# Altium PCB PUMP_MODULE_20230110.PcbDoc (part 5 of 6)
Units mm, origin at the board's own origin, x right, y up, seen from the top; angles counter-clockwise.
Board outline 260.15 x 142.01 mm, 4 copper layers (Top Layer, Mid-Layer 1, Mid-Layer 2, Bottom Layer); 422 components, 240 nets, 1746 pads, 416 vias.
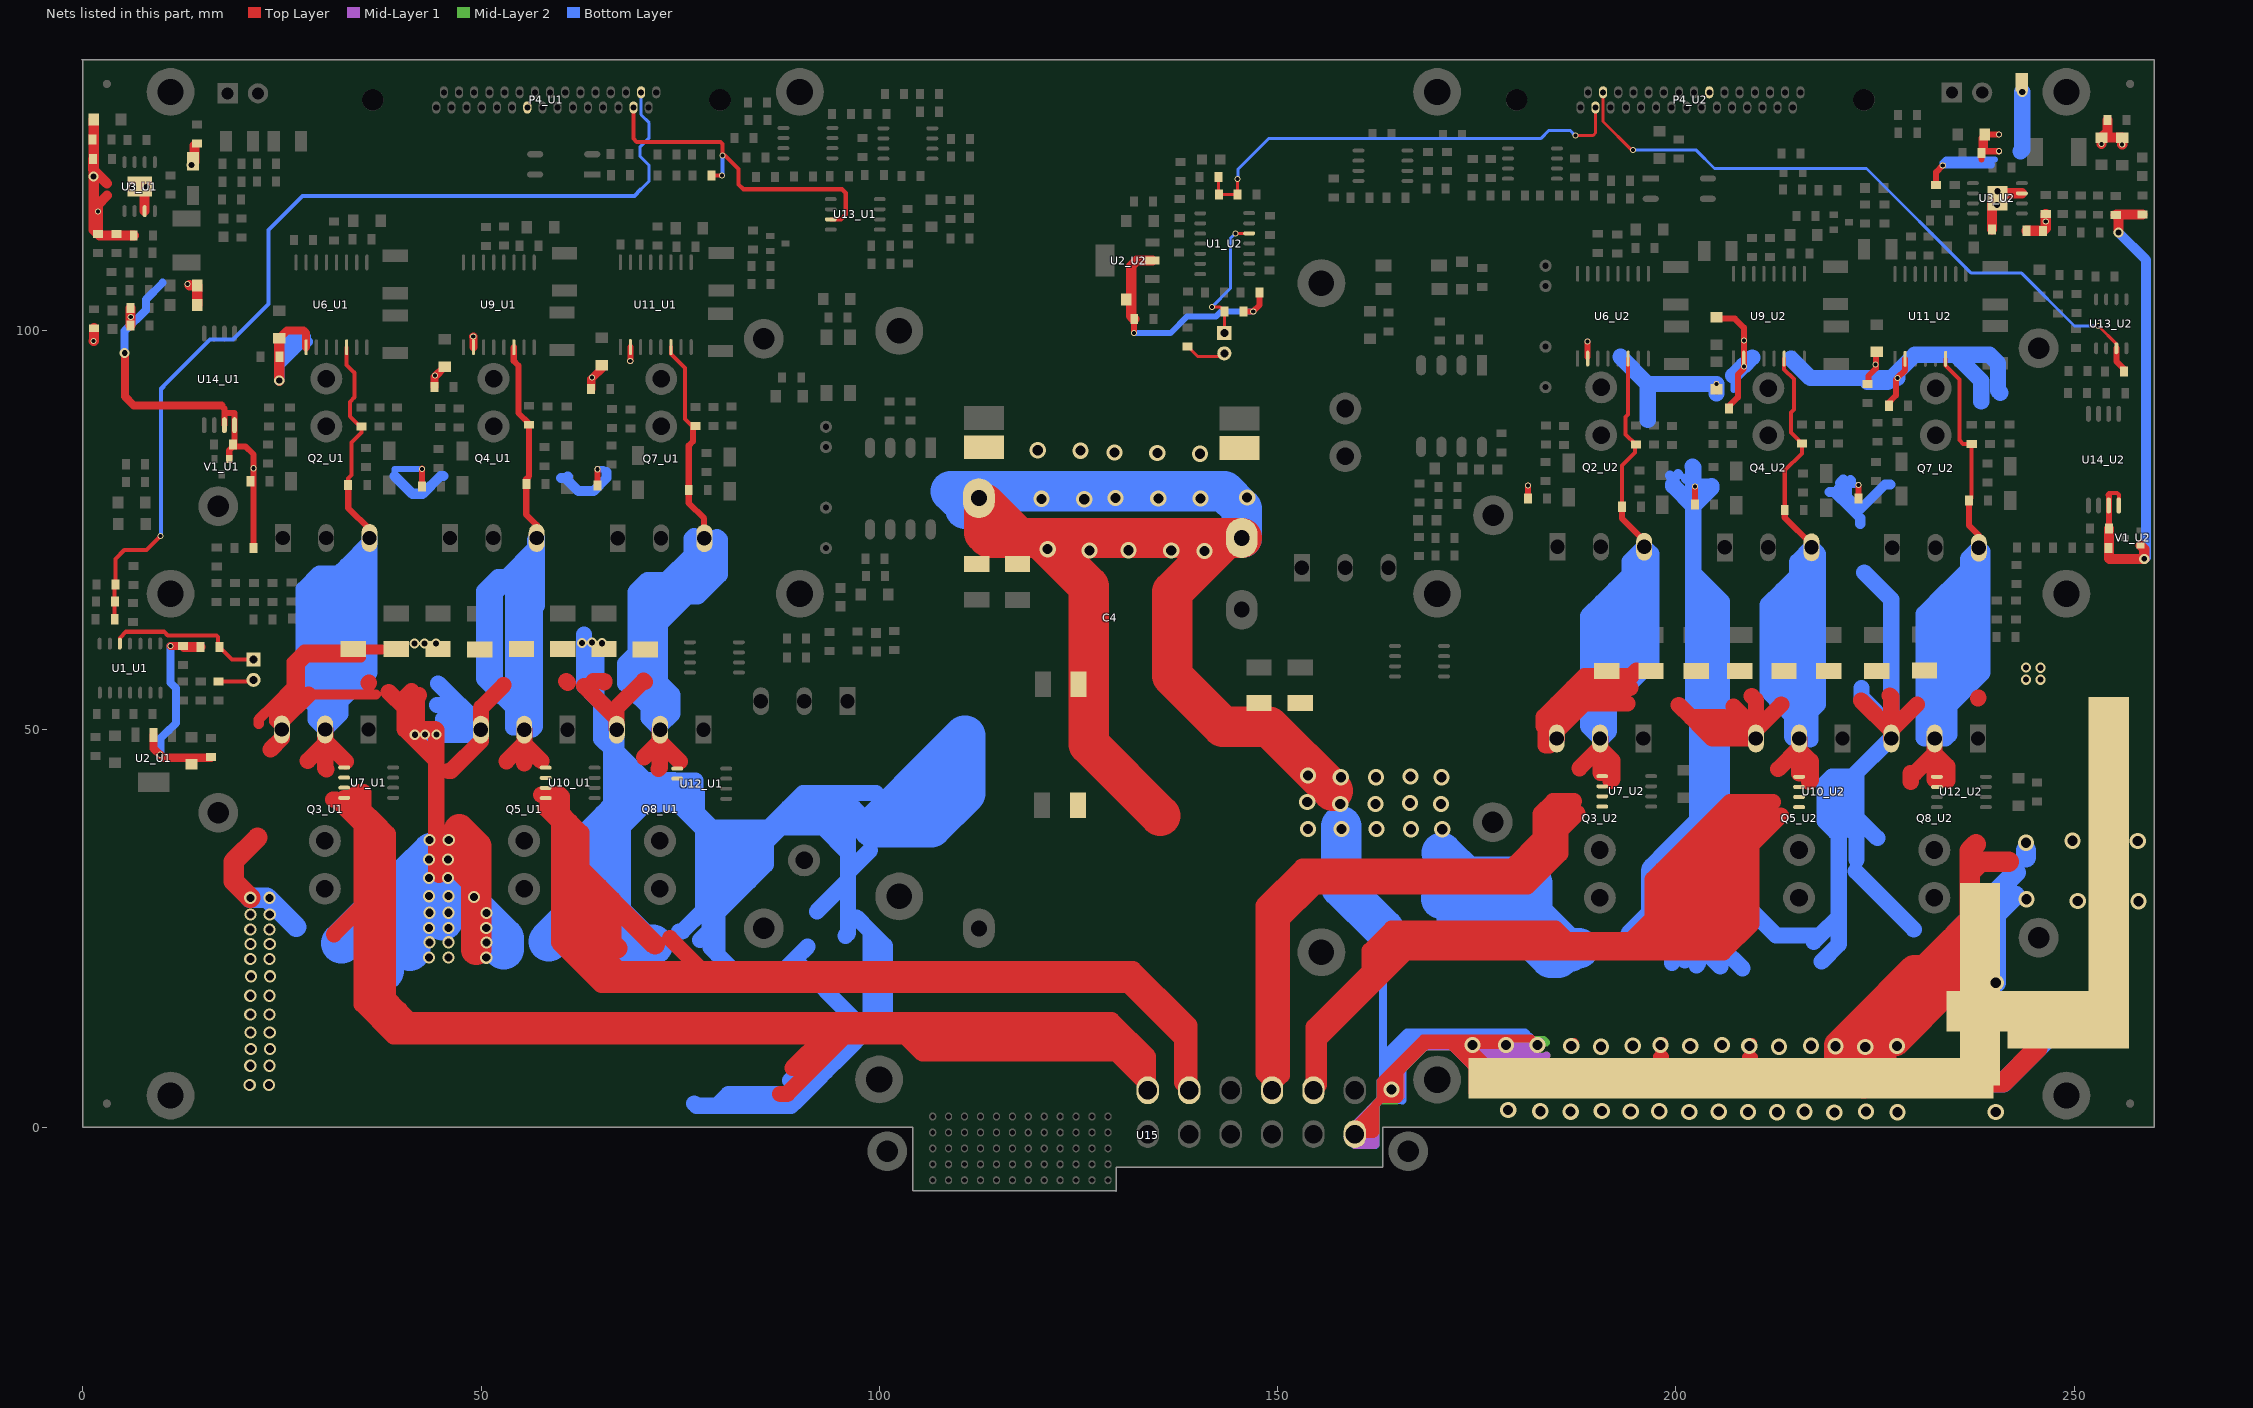
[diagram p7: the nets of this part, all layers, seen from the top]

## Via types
v1: diameter 0.762, hole 0.508, Top Layer to Bottom Layer, 208 vias
v2: diameter 2.032, hole 1.27, Top Layer to Bottom Layer, 78 vias
v3: diameter 1.27, hole 0.762, Top Layer to Bottom Layer, 61 vias
v4: diameter 1.524, hole 1.016, Top Layer to Bottom Layer, 53 vias
v5: diameter 1.27, hole 0.711, Top Layer to Bottom Layer, 16 vias

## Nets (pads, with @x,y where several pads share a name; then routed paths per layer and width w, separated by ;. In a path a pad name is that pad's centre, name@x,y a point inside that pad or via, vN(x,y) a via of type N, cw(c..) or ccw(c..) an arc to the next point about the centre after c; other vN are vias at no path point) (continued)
PGND: C4.2 C15_U1.1 C15_U2.1 C16_U1.1 C16_U2.1 C17.1 C18.1 C19_U1.2 C19_U2.2 C20_U1.1 C20_U2.1 C21_U1.2 C21_U2.2 C22_U1.2 C22_U2.2 C24_U1.2 C24_U2.2 C25_U1.1 C25_U2.1 C26_U1.1 C26_U2.1 C27_U1.1 C27_U2.1 C29_U1.1 C29_U2.1 C30_U1.1 C30_U2.1 C43_U1.2 C43_U2.2 C44_U1.2 C44_U2.2 C51_U1.2 C51_U2.2 C52_U1.2 C52_U2.2 C68_U1.2 C68_U2.2 C69_U1.1 C69_U2.1 C70_U1.1 C70_U2.1 C71_U1.1 C71_U2.1 C72_U1.1 C72_U2.1 C73.1 C74.1 C75.1 C76.1 C77_U1.1 C77_U2.1 C78_U1.1 C78_U2.1 D2_U1.1 D2_U2.1 pad.@186.665,6.172 pad.@210.414,6.172 pad.@227.203,6.172 pad.@238.176,17.958 pad.@244.145,14.58 pad.@249.276,12.446 pad.@254.356,24.765 pad.@254.356,41.326 Q3_U1.3 Q3_U2.3 Q5_U1.3 Q5_U2.3 Q8_U1.3 Q8_U2.3 R16_U1.2 R16_U2.2 R21_U1.2 R21_U2.2 R22_U1.1 R22_U2.1 R24_U1.2 R24_U2.2 R25_U1.1 R25_U2.1 R37_U1.1 R37_U2.1 R54_U1.1 R54_U2.1 R68_U1.1 R68_U2.1 R78_U1.2 R78_U2.2 U3_U1.7 U3_U1.9 U3_U2.7 U3_U2.9 U6_U1.2 U6_U2.2 U9_U1.2 U9_U2.2 U11_U1.2 U11_U2.2 U14_U1.3 U14_U1.4 U14_U2.3 U14_U2.4 U15.12 V1_U1.1 V1_U2.1 | length 2564
  Top Layer w0.508: C69_U2.1@254.305,72.72 C69_U2.1@254.33,72.746 ; U14_U2.3@254.33,78.08 254.33,79.375 254.229,79.477 254.381,79.629 255.397,79.629 255.6,79.426 U14_U2.4@255.6,78.08
  Top Layer w0.762: 17.399,90.627 17.78,90.246 17.78,89.433 ; U14_U1.3@17.78,88.163 17.78,89.433 ; V1_U1.1@18.39,83.896 18.39,84.988 C69_U1.1@18.898,85.496 ; R37_U1.1@21.057,81.128 R37_U1.1@21.438,80.747 ; R78_U1.2@21.438,72.746 R37_U1.1@21.438,80.747 ; 24.663,95.58 24.79,95.58 ; R54_U1.1@42.57,80.467 42.57,82.702 v1(42.596,82.677) ; v1(64.618,82.626) 64.618,82.677 64.643,82.652 R68_U1.1@64.643,80.569 ; v1(68.732,96.241) 68.758,96.266 U11_U1.2@68.758,97.968 ; R37_U2.1@181.407,78.943 v1(181.407,80.569) ; U6_U2.2@188.925,96.723 v1(188.925,98.654) ; R54_U2.1@202.387,78.181 v1(202.387,80.442) ; C43_U2.2@205.08,92.405 v1(205.08,93.32) ; C51_U2.2@205.08,101.702 205.232,101.549 207.391,101.549 208.534,100.406 v1(208.534,98.781) v1(208.534,95.529) 208.534,95.504 208.509,95.479 208.509,95.25 207.772,94.513 207.772,91.669 C44_U2.2@206.68,90.576 ; R68_U2.1@222.936,78.943 v1(222.936,80.67) ; C68_U2.2@224.18,93.751 224.18,94.361 225.12,95.301 C19_U2.2@225.12,97.358 ; C52_U2.2@226.644,90.907 227.635,91.897 227.635,93.904 v1(227.813,94.082) ; v1@227.8,94.094 228.778,95.072 U11_U2.2@228.778,96.495 ; R24_U2.2@232.664,118.313 232.664,119.939 v1(233.502,120.777) ; 238.379,121.539 C25_U2.1@238.379,122.352 ; v1(240.538,122.555) C25_U2.1@238.582,122.555 ; v1(240.538,124.638) C24_U2.2@238.785,124.638 ; 254.33,79.375 254.381,79.324 R78_U2.2@254.381,75.209 ; 17.78,89.433 18.059,89.713 19.025,89.713 19.05,89.687 U14_U1.4@19.05,88.163 19.05,85.649 C69_U1.1@18.898,85.496 ; C69_U1.1@18.898,85.496 20.422,85.496 21.438,84.48 R37_U1.1@21.438,80.747 ; C25_U2.1@238.379,122.352 C25_U2.1@238.582,122.555 ; C25_U2.1@238.379,122.352 238.379,124.231 C24_U2.2@238.785,124.638 ; C25_U2.1@238.582,122.555 238.785,122.758 C24_U2.2@238.785,124.638
  Top Layer w1.016: v5(5.258,97.231) 5.283,97.206 5.283,91.745 6.401,90.627 17.399,90.627 ; C43_U1.2@24.663,99.085 25.629,100.051 27.711,100.051 28.042,99.72 U6_U1.2@28.042,97.942 ; C44_U1.2@44.145,92.964 44.145,94.209 C51_U1.2@45.441,95.504 ; v1(49.022,99.314) 49.047,99.289 U9_U1.2@49.047,97.942 ; C52_U1.2@63.83,92.71 63.83,93.955 65.354,95.479 C19_U1.2@65.354,95.733 ; pad.@174.473,7.569 171.679,10.363 ; pad.@176.098,6.934 176.098,7.315 174.6,8.814 174.473,8.941 ; pad.@176.53,7.798 174.6,9.728 v2@174.473,9.855 ; v2@178.943,10.109 v2(178.689,10.363) v2(174.473,10.363) ; v2(182.626,10.363) 181.839,11.151 168.758,11.151 ; U15.12@159.741,-0.837 159.741,0.204 162.286,2.748 ; U15.12@159.741,-0.837 U15.12@160.934,-0.837 ; U15.12@159.741,-0.837 162.286,1.707 ; U15.12@160.934,-0.837 162.028,-0.837 162.286,-0.579 162.286,0.514 ; U15.12@160.934,-0.837 162.286,0.514 ; 162.286,0.514 162.286,1.707 ; 162.286,1.707 162.286,2.748 ; 162.286,2.748 162.286,2.894 162.973,3.581 ; 162.973,3.581 162.973,5.849 168.275,11.151 168.758,11.151 ; 162.973,3.581 163.373,3.981 163.373,5.766 164.313,6.706 ; 162.973,3.581 163.119,3.581 ; 163.119,3.581 165.1,3.581 165.303,3.785 165.303,6.96 ; 163.119,3.581 v2(164.313,4.775) 164.313,6.706 ; 164.313,6.706 165.303,7.696 ; 165.303,6.96 165.303,7.696 ; 165.303,6.96 168.707,10.363 ; 165.303,7.696 167.97,10.363 ; 167.97,10.363 168.707,10.363 ; 167.97,10.363 168.758,11.151 ; 168.707,10.363 171.679,10.363 ; 171.679,10.363 173.05,10.363 ; 173.05,10.363 174.473,8.941 ; 173.05,10.363 v2(174.473,10.363) ; 174.473,8.941 v2@174.473,9.855 ; v2@174.473,9.855 v2(174.473,10.363)
  Top Layer w1.27: C26_U1.1@1.295,121.59 1.295,120.244 1.372,120.167 ; v1(1.372,98.73) 1.422,98.781 R16_U1.2@1.422,100.33 ; C24_U1.2@1.372,126.517 1.372,120.167 ; 3.023,118.516 1.372,120.167 ; 3.048,116.992 1.93,115.875 v1(1.93,114.986) ; C29_U1.1@5.969,102.87 5.994,102.845 C30_U1.1@5.994,100.686 ; C27_U1.1@6.401,111.963 2.108,111.963 R22_U1.1@1.93,112.141 ; U3_U1.9@7.163,118.11 7.772,117.5 U3_U1.7@7.772,115.037 ; v1@13.411,105.74 13.437,105.715 C21_U1.2@14.376,105.715 C22_U1.2@14.376,103.251 ; D2_U1.1@14.046,121.209 C25_U1.1@14.046,123.292 ; 22.098,50.648 22.098,51.232 24.003,53.137 ; C43_U1.2@24.663,99.085 24.663,95.58 v3(24.663,93.751) v3@24.689,93.726 ; 34.95,59.03 28.296,59.03 28.27,59.055 27.28,58.064 27.28,55.194 26.416,54.331 ; 36.779,54.331 28.346,54.331 26.416,54.331 ; 37.49,60.02 27.788,60.02 26.238,58.471 26.238,55.372 24.003,53.137 ; 174.473,8.941 174.473,7.569 pad.@174.6,7.442 ; v2@174.6,9.728 174.6,8.814 pad.@174.6,7.442 ; v2(186.868,10.236) v2@187.198,10.566 ; 197.764,8.915 198.526,8.915 198.069,9.373 v2(198.069,10.338) v2@198.399,10.668 ; 208.915,8.814 209.677,8.814 209.22,9.271 v2(209.22,10.236) v2@209.55,10.566 ; 219.735,8.763 220.497,8.763 220.04,9.22 v2(220.04,10.185) v2@220.37,10.516 ; C26_U2.1@239.7,112.751 239.7,116.002 U3_U2.9@240.36,116.662 240.97,117.272 U3_U2.7@243.434,117.272 ; R22_U2.1@244.043,112.573 246.024,112.573 R25_U2.1@246.075,112.522 246.431,112.878 v1(246.431,113.716) C27_U2.1@246.431,114.681 ; v1(253.416,123.444) C21_U2.2@253.416,124.257 ; C30_U2.1@254.178,126.492 254.178,125.019 C21_U2.2@253.416,124.257 ; R78_U2.2@254.381,75.209 254.356,75.184 254.356,71.45 254.432,71.374 v5(258.801,71.374) 258.801,72.593 V1_U2.1@258.318,73.076 ; C29_U2.1@255.219,114.554 C29_U2.1@255.295,114.63 ; v5(255.575,112.344) 255.575,114.351 C29_U2.1@255.295,114.63 ; v1(256.032,123.419) C22_U2.2@256.032,124.231 256.007,124.257 C21_U2.2@253.416,124.257 ; R16_U2.2@258.572,114.63 C29_U2.1@255.295,114.63 ; 1.372,115.545 1.372,120.167 ; 1.372,115.545 1.372,112.7 R22_U1.1@1.93,112.141 ; 1.372,115.545 v1(1.93,114.986) ; R22_U1.1@1.93,112.141 v1(1.93,114.986) ; 24.003,52.019 24.003,50.997 25,50 25,50.984 Q3_U1.3@25,51.022 ; 24.003,52.019 Q3_U1.3@25,51.022 ; 24.003,52.019 24.003,53.137 ; Q3_U1.3@25,51.022 25,52.915 26.416,54.331 ; pad.@174.6,7.442 174.6,4.369 175.362,4.369 174.904,4.826 174.904,5.791 175.235,6.121 175.235,6.807 pad.@174.6,7.442
  Top Layer w2.032: 23.571,47.447 25,48.876 Q3_U1.3@25,50 ; Q3_U1.3@25,50.984 28.346,54.331 ; 35.88,55.794 35.916,55.829 ; 38.405,54.661 40.399,52.667 ; 41.275,54.788 40.399,53.911 40.399,52.667 ; 42.215,54.254 41.961,54 41.961,50 ; 44.729,31.725 44.374,32.08 44.374,46.025 ; 45.974,44.729 45.949,44.729 45.923,44.755 46.228,44.755 50,48.527 50,52.692 52.832,55.524 ; 60.706,56.007 60.88,55.833 ; 62.941,55.423 Q8_U1.3@67,51.364 ; 64.135,56.058 65.456,56.058 65.456,55.88 ; Q8_U1.3@67,50 Q8_U1.3@67,51.364 ; 70.561,55.931 70.409,56.083 67,52.674 Q8_U1.3@67,51.364 ; 189.255,53.213 188.493,53.213 ; 193.929,53.213 188.493,53.213 ; 194.259,55.194 187.046,55.194 ; 195.047,57.328 194.412,56.693 188.544,56.693 187.046,55.194 ; 200.355,53.035 201.905,51.486 ; 207.239,52.832 Q5_U2.3@210.041,50.029 ; 209.525,54.153 210.041,53.636 Q5_U2.3@210.041,50.029 ; 213.233,53.086 Q5_U2.3@210.041,49.894 ; 223.241,53.594 Q8_U2.3@227.041,49.793 ; 226.847,54.229 227.041,54.035 Q8_U2.3@227.041,49.876 ; Q8_U2.3@227.041,48.83 Q8_U2.3@227.041,49.793 ; 230.251,53.086 Q8_U2.3@227.041,49.876 ; 237.921,53.873 237.998,53.95 ; 40.399,50 44.374,46.025 ; 40.399,50 41.961,50 ; 40.399,50 40.399,52.667 ; 41.961,50 44.259,50 44.374,49.886 44.374,46.025 ; Q3_U2.3@185.041,49.761 185.041,51.234 ; Q3_U2.3@185.041,49.761 188.493,53.213 ; Q3_U2.3@185.041,49.761 Q3_U2.3@185.041,48.83 184.167,47.955 183.667,47.955 183.667,50.114 183.413,50.368 183.413,51.562 185.041,53.19 ; 185.041,51.234 185.041,53.19 ; 185.041,51.234 187.02,53.213 188.493,53.213 ; 185.041,53.19 187.046,55.194 ; 201.905,51.486 203.467,49.924 ; 201.905,51.486 205.969,51.486 207.531,49.924 ; 203.467,49.924 204.561,48.83 208.625,48.83 ; 203.467,49.924 207.531,49.924 ; 207.531,49.924 208.625,48.83 ; 208.625,48.83 Q5_U2.3@210.041,48.83 Q5_U2.3@210.041,49.894 ; Q5_U2.3@210.041,49.894 Q5_U2.3@210.041,50.029 ; Q8_U2.3@227.041,49.793 Q8_U2.3@227.041,49.876
  Top Layer w2.54: v4(21.031,28.829) 18.948,30.912 18.948,33.401 21.946,36.398 ; pad.@227.559,5.639 241.071,5.639 pad.@245.364,9.931 ; v2(227.762,10.211) 234.772,17.221 234.772,21.641 ; 234.772,23.19 234.772,24.079 236.88,26.187 236.88,31.953 ; 237.668,35.56 236.88,34.773 236.88,31.953 ; 241.833,33.35 238.277,33.35 236.88,31.953
  Top Layer w3.81: 45.491,34.849 45.542,34.849 49.403,30.988 ; 47.269,37.44 49.403,35.306 49.403,30.988 ; 49.403,22.276 49.403,30.988 ; pad.@223.571,5.512 v2@223.571,10.439 ; pad.@225.806,7.772 225.806,12.675 ; 234.772,21.641 225.806,12.675 ; 234.772,23.19 231.343,19.761 229.921,19.761 223.571,13.411 ; v2@223.571,10.439 221.894,8.763 220.497,8.763 220.497,10.338 223.571,13.411 ; v2@223.571,10.439 225.806,12.675 ; v2@223.571,10.439 223.571,13.411
  Top Layer w5.08: 117.5,74 113.182,78.318 113.182,74.651 113.833,74 C4.2@143.545,74 ; 120.208,74 126.289,67.92 126.289,48.133 135.28,39.141 ; C4.2@145.5,74 C4.2@143.545,74 ; 156.947,42.291 148.92,50.317 143.129,50.317 136.754,56.693 136.754,67.234 136.779,67.234 C4.2@143.545,74
  Mid-Layer 1 w1.016: U15.12@158.775,-1.27 159.69,-2.184 162.179,-2.184 162.286,-2.078 162.286,-0.833 ; U15.12@159.7,-0.837 160.438,-1.575 161.544,-1.575 162.286,-0.833 ; 165.456,6.807 165.456,5.105 ; 168.834,10.185 171.806,10.185 170.891,11.1 ; 172.06,10.185 173.304,10.185 174.676,8.814 183.54,8.814 183.744,9.017 ; U15.12@159.741,-0.837 159.741,0.349 162.286,2.894 ; U15.12@159.741,-0.837 162.286,1.707 ; U15.12@159.741,-0.837 160.935,-0.837 162.286,0.513 ; 162.286,-0.833 162.286,0.513 ; 162.286,0.513 162.286,1.707 ; 162.286,1.707 162.286,2.894 ; 162.286,2.894 162.944,3.553 ; 162.944,3.553 162.944,5.82 163.551,6.426 ; 162.944,3.553 v2@163.551,4.159 ; 162.944,3.553 163.551,3.553 ; 163.551,3.553 164.385,3.553 ; 163.551,3.553 v2@163.551,4.159 ; v2@163.551,4.159 163.551,6.426 ; v2@163.551,4.159 164.167,4.775 v2(164.313,4.775) ; 163.551,6.426 168.224,11.1 168.732,11.1 ; v2(164.313,4.775) 165.125,4.775 165.456,5.105 ; v2(164.313,4.775) v2@164.313,5.258 ; v2(164.313,4.775) 164.313,3.734 164.44,3.607 164.385,3.553 ; v2@164.313,5.258 164.313,6.68 164.821,7.188 ; v2@164.313,5.258 164.821,5.766 164.821,7.188 ; 164.385,3.553 165.147,3.553 165.456,3.861 165.456,5.105 ; 164.821,7.188 168.732,11.1 ; 168.732,11.1 170.891,11.1 ; 170.891,11.1 181.889,11.1 v2(182.626,10.363) ; v2(182.626,10.363) 181.635,9.373 175.463,9.373 v2(174.473,10.363) v2(178.689,10.363) v2(182.626,10.363) ; 165.456,7.112 168.529,10.185 168.072,10.185 165.456,7.569 165.456,7.112
  Mid-Layer 1 w1.27: 172.06,10.185 175.362,6.883 175.362,6.248
  Mid-Layer 2 w1.016: U15.12@158.877,-1.372 159.664,-2.159 162.23,-2.159 162.286,-2.103 162.286,-0.859 ; U15.12@159.7,-0.837 159.7,0.308 162.286,2.894 ; 162.806,3.414 163.347,3.414 ; 162.966,3.574 162.966,5.766 163.5,6.299 ; 165.405,6.7 165.405,3.962 165.049,3.607 ; 168.865,10.16 171.958,10.16 ; 175.158,5.385 175.158,6.96 171.958,10.16 ; 183.617,8.915 174.473,8.915 173.228,10.16 171.958,10.16 ; 183.718,10.643 183.388,10.973 171.145,10.973 ; U15.12@159.741,-0.837 159.741,0.255 162.286,2.799 ; U15.12@159.741,-0.837 U15.12@159.818,-0.914 ; U15.12@159.741,-0.837 159.996,-0.837 162.286,1.453 ; U15.12@159.818,-0.914 160.098,-1.194 161.95,-1.194 162.286,-0.859 ; U15.12@159.818,-0.914 161.315,-0.914 162.286,0.056 ; 162.286,-0.859 162.286,0.056 ; 162.286,0.056 162.286,1.453 ; 162.286,1.453 162.286,2.799 ; 162.286,2.799 162.286,2.894 ; 162.286,2.894 163.5,4.108 ; 163.347,3.414 164.338,3.414 ; 163.347,3.414 163.5,3.567 163.5,4.108 ; 163.5,4.108 163.5,6.299 ; 163.5,4.108 164.167,4.775 v2(164.313,4.775) ; 163.5,6.299 164.313,7.112 ; v2(164.313,4.775) v2@164.313,5.613 ; v2(164.313,4.775) 165.024,4.775 165.049,4.801 165.049,3.607 ; v2(164.313,4.775) 164.338,4.75 164.338,3.414 ; v2@164.313,5.613 164.313,7.112 ; v2@164.313,5.613 164.795,6.096 164.795,7.595 ; 164.313,7.112 164.795,7.595 ; 164.338,3.414 164.857,3.414 165.049,3.607 ; 164.795,7.595 168.173,10.973 171.145,10.973 ; 171.145,10.973 171.958,10.16 ; 165.405,7.061 168.504,10.16 168.097,10.16 165.405,7.468 165.405,7.061 ; v2@174.473,10.008 174.777,9.703 181.966,9.703 v2(182.626,10.363) v2(178.689,10.363) v2(174.473,10.363) v2@174.473,10.008
  Bottom Layer w0.762: 39.167,81.763 39.167,82.652 39.192,82.677 v1(42.596,82.677) ; v1(64.618,82.626) 65.38,82.626 65.761,82.245 ; 207.239,92.583 207.239,94.234 v1(208.534,95.529) 208.483,95.58 v1@208.432,95.631 ; 221.488,80.594 221.564,80.67 v1(222.936,80.67) ; 239.7,120.879 239.598,120.777 v1(233.502,120.777) 233.502,121.107 233.934,121.539 240.03,121.539
  Bottom Layer w1.016: v5(5.258,97.231) 5.258,99.974 7.925,102.641 7.925,103.937 10.033,106.045 ; U15.12@158.902,-1.422 159.664,-2.184 161.047,-2.184 ; U15.12@159.284,-0.837 U15.12@159.7,-0.837 161.047,-2.184 ; 163.525,20.676 163.22,20.371 163.22,8.915 ; v2@163.805,4.191 163.779,4.216 v2@163.779,4.387 ; 175.387,8.128 174.473,9.042 ; U15.12@159.741,-0.837 159.741,0.28 161.011,1.549 ; U15.12@159.741,-0.837 160.479,-1.575 161.798,-1.575 162.286,-1.087 ; U15.12@159.741,-0.837 161.011,0.432 161.011,1.549 ; U15.12@159.741,-0.837 U15.12@160.529,-0.837 ; U15.12@160.529,-0.837 161.977,-0.837 162.286,-0.528 ; U15.12@160.529,-0.837 161.62,0.254 161.62,2.159 ; 161.011,1.549 161.62,2.159 ; 161.047,-2.184 162.286,-2.184 162.286,-1.087 ; 161.62,2.159 161.62,2.228 162.286,2.894 ; 162.286,-1.087 162.286,-0.528 ; 162.286,-0.528 162.286,2.894 ; 162.286,2.894 162.881,3.489 ; 162.881,3.489 163.068,3.676 ; 162.881,3.489 162.941,3.429 164.135,3.429 ; 163.068,3.676 v2@163.779,4.387 ; 163.068,3.676 163.068,4.623 163.22,4.775 ; 163.22,4.775 163.22,8.915 ; 163.22,4.775 v2@163.779,4.775 ; 163.22,8.915 166.243,11.938 167.335,11.938 ; v2@163.779,4.387 v2@163.779,4.775 ; v2@163.779,4.387 v2@164.167,4.775 ; v2@163.779,4.775 163.779,8.357 164.313,7.823 ; v2@163.779,4.775 v2@164.167,4.775 ; 164.135,3.429 165.151,3.429 ; 164.135,3.429 164.313,3.607 v2(164.313,4.775) ; v2@164.167,4.775 v2(164.313,4.775) ; v2(164.313,4.775) 164.313,7.671 ; v2(164.313,4.775) 165.075,4.775 v2@165.151,4.699 ; 164.313,7.671 167.475,10.833 ; 164.313,7.671 164.313,7.823 ; 164.313,7.823 164.313,8.915 167.335,11.938 ; 165.151,3.429 165.644,3.429 165.659,3.414 165.659,7.315 168.631,10.287 ; 165.151,3.429 v2@165.151,4.699 ; v2@165.151,4.699 165.151,7.214 168.224,10.287 168.631,10.287 ; 167.335,11.938 181.051,11.938 181.661,11.328 ; 167.475,10.833 171.59,10.833 ; 167.475,10.833 167.97,11.328 171.094,11.328 ; 168.631,10.287 172.136,10.287 ; 171.094,11.328 181.661,11.328 ; 171.094,11.328 171.59,10.833 ; 171.59,10.833 174.003,10.833 v2(174.473,10.363) ; 171.59,10.833 172.136,10.287 ; 172.136,10.287 172.136,9.957 174.473,7.62 174.473,9.042 ; 172.136,10.287 173.228,10.287 174.473,9.042 ; 174.473,9.042 v2(174.473,10.363) ; v2(174.473,10.363) v2(178.689,10.363) v2(182.626,10.363) 181.661,11.328
  Bottom Layer w1.27: v3(24.663,93.751) 24.663,95.682 ; 24.714,96.749 24.714,96.977 ; 27.991,99.289 26.035,99.289 24.714,97.968 24.714,96.977 ; 28.296,98.628 27.61,98.628 ; 39.167,81.763 41.377,79.553 42.672,79.553 44.907,81.788 45.288,81.788 ; 60.071,81.534 60.579,81.534 62.23,79.883 64.11,79.883 65.761,81.534 65.761,82.245 ; 60.808,81.636 60.884,81.712 ; 199.238,81.839 199.593,81.483 ; 200.279,82.017 200.33,81.966 ; 201.295,81.432 201.524,81.661 ; 219.278,79.756 219.888,79.756 221.945,77.699 ; 220.421,80.188 220.472,80.188 221.488,79.172 ; 220.624,80.924 221.005,81.305 221.158,81.153 ; 221.488,80.594 221.488,79.172 ; 221.92,81.255 221.983,81.191 ; 223.139,75.794 223.139,76.505 221.945,77.699 ; 226.924,80.721 226.263,80.721 223.495,77.953 ; v5(255.575,112.344) 259.007,108.912 259.007,71.58 v5(258.801,71.374) ; 24.663,95.682 27.61,98.628 ; 24.663,95.682 24.663,96.926 24.714,96.977 ; 24.714,96.977 26.365,98.628 27.61,98.628 ; 221.488,79.172 222.707,77.953 223.495,77.953 ; 221.945,77.699 223.241,77.699 223.495,77.953
  Bottom Layer w2.032: v3(41.681,49.301) 49.343,49.301 Q5_U1.3@49.978,49.936 Q5_U1.3@49.978,50.352 ; 44.45,53.035 47.295,53.035 ; 44.602,55.728 47.295,53.035 ; 45.263,51.257 45.339,51.181 Q5_U1.3@49.149,51.181 ; 62.941,61.9 62.941,55.448 64.491,53.899 ; 64.491,60.071 64.491,53.899 ; 66.281,38.367 66.319,38.405 ; Q8_U1.3@67,50 Q8_U1.3@67,49.271 ; 70.002,42.088 68.758,43.332 68.758,45.466 ; 74.854,24.613 75.26,24.613 77.88,27.232 77.88,30.705 ; 76.759,3.023 77.064,2.718 88.925,2.718 89.357,3.15 ; 77.47,23.52 78.664,24.714 78.664,25.883 ; 78.791,22.606 79.654,21.742 ; 79.172,32.741 80.874,32.741 ; 90.983,22.708 89.624,21.349 ; 91.999,12.116 92.316,11.798 92.316,8.585 ; 92.177,27.127 96.063,31.013 ; 95.656,12.649 93.294,10.287 93.294,8.585 ; 95.733,24.054 96.063,24.384 96.063,31.013 ; 97.13,26.365 98.882,24.613 ; 98.831,34.798 96.063,32.029 ; 99.568,41.986 90.424,41.986 88.57,40.132 ; 193.04,96.749 196.469,93.32 ; 196.469,88.824 196.469,93.32 ; 199.492,20.625 199.492,34.163 199.492,34.493 200.177,35.179 ; 199.644,80.721 199.644,80.543 202.184,78.003 ; 201.117,20.98 200.965,21.133 200.965,33.172 202.006,34.214 203.606,34.214 204.546,35.154 ; 202.082,82.956 202.184,82.855 202.184,78.003 ; v1(202.387,80.442) 204.394,80.442 204.47,80.518 204.47,80.289 202.184,78.003 ; 202.59,20.371 202.794,20.574 202.794,32.283 204.546,34.036 ; 205.08,92.126 v1(205.08,93.32) 196.469,93.32 ; 205.562,20.193 204.546,21.209 204.546,34.036 ; 207.188,94.386 v1@208.432,95.631 ; 208.356,19.99 205.765,22.581 205.765,28.524 205.765,32.868 205.765,35.255 ; v1@208.483,95.58 209.575,96.672 ; 209.55,27.127 212.585,24.092 218.072,24.092 ; Q5_U2.3@210.041,48.83 205.765,53.106 ; 214.452,96.52 216.891,94.082 227.076,94.082 ; 217.297,23.317 218.072,24.092 ; 218.288,20.828 220.447,22.987 220.447,26.467 ; 222.199,37.135 220.002,39.332 ; 222.58,32.156 229.87,24.867 ; 222.656,33.604 222.656,38.964 ; 222.656,36.805 220.921,38.54 220.921,42.791 ; 223.317,55.169 223.317,53.975 Q8_U2.3@227.041,50.25 ; 223.647,69.672 227.041,66.278 Q8_U2.3@227.041,50.25 ; 224.053,93.599 226.593,93.599 227.076,94.082 ; 225.298,36.322 222.656,38.964 ; Q8_U2.3@226.644,48.514 222.656,44.526 ; Q8_U2.3@227.041,48.83 Q8_U2.3@227.041,50.25 ; 238.328,91.135 238.328,93.726 235.052,97.003 ; 240.716,92.227 240.436,92.507 240.436,95.936 239.37,97.003 235.052,97.003 ; 243.281,122.555 243.484,122.758 v3(243.484,129.997) ; 47.295,53.035 47.396,53.035 Q5_U1.3@49.251,51.181 ; 47.295,53.035 Q5_U1.3@49.149,51.181 ; Q5_U1.3@49.149,51.181 Q5_U1.3@49.978,50.352 ; Q5_U1.3@49.149,51.181 Q5_U1.3@49.251,51.181 ; Q5_U1.3@49.251,51.181 Q5_U1.3@49.978,50.453 ; Q5_U1.3@49.251,51.181 49.454,51.181 49.978,50.656 Q5_U1.3@49.978,50.453 ; Q5_U1.3@49.978,50.352 Q5_U1.3@49.978,50.453 ; 64.491,53.899 65.075,53.315 ; 65.075,53.315 65.075,48.768 66.319,47.523 ; 65.075,53.315 66.319,52.07 Q8_U1.3@66.319,48.59 ; 66.319,38.405 66.319,47.523 ; 66.319,38.405 67,39.085 67,47.224 ; 66.319,47.523 66.619,47.224 67,47.224 ; 66.319,47.523 Q8_U1.3@66.319,48.59 ; Q8_U1.3@66.319,48.59 Q8_U1.3@67,49.271 ; 67,47.224 Q8_U1.3@67,49.271 ; 67,47.224 68.758,45.466 ; 68.758,45.466 72.136,42.088 73.177,42.088 ; 73.177,42.088 74.651,43.561 76.937,43.561 76.937,42.215 77.114,42.037 77.114,39.522 77.88,38.757 ; 73.177,42.088 77.88,37.385 ; 77.88,30.705 78.664,29.921 ; 77.88,30.705 77.88,36.09 ; 77.88,36.09 77.88,37.385 ; 77.88,36.09 80.874,33.096 ; 77.88,37.385 77.88,38.757 ; 77.88,37.385 78.163,37.668 78.969,37.668 ; 77.88,38.757 78.969,37.668 ; 78.664,25.883 79.654,26.873 ; 78.664,25.883 78.664,29.921 ; 78.664,29.921 79.654,28.931 ; 78.969,37.668 80.874,35.763 ; 78.969,37.668 86.106,37.668 ; 79.654,21.742 81.737,19.66 87.935,19.66 89.624,21.349 ; 79.654,21.742 79.654,26.873 ; 79.654,26.873 83.668,30.886 ; 79.654,26.873 79.654,27.991 ; 79.654,27.991 79.654,28.931 ; 79.654,27.991 80.874,29.21 80.874,30.886 ; 79.654,28.931 79.654,31.267 80.874,32.487 ; 80.874,30.886 82.728,32.741 ; 80.874,30.886 80.874,32.41 ; 80.874,30.886 83.668,30.886 ; 80.874,32.41 80.874,32.487 ; 80.874,32.41 81.204,32.741 ; 80.874,32.487 80.874,32.741 ; 80.874,32.741 80.874,33.096 ; 80.874,32.741 81.204,32.741 ; 80.874,33.096 80.874,35.763 ; 80.874,35.763 84.226,35.763 ; 81.204,32.741 84.226,35.763 ; 81.204,32.741 82.728,32.741 ; 82.728,32.741 85.75,35.763 ; 83.668,30.886 85.75,32.969 85.75,35.763 ; 84.226,35.763 85.75,35.763 ; 85.75,35.763 87.655,37.668 ; 86.106,37.668 87.655,37.668 ; 86.106,37.668 87.592,39.154 ; 87.592,39.154 97.777,39.154 ; 87.592,39.154 88.57,40.132 ; 87.655,37.668 92.913,37.668 ; 88.57,40.132 96.799,40.132 97.777,39.154 ; 89.357,3.15 89.408,3.15 92.316,6.058 ; 89.357,3.15 80.01,3.15 81.026,4.166 89.357,4.166 ; 89.357,3.15 89.357,4.166 ; 89.357,4.166 89.357,5.334 88.798,5.893 91.491,8.585 92.316,8.585 ; 89.624,21.349 89.624,20.841 96.799,13.665 96.799,11.024 95.25,9.474 ; 92.316,6.058 93.294,7.036 ; 92.316,6.058 92.316,8.585 ; 92.316,8.585 93.294,8.585 ; 92.913,37.668 96.063,34.519 ; 92.913,37.668 96.215,37.668 ; 93.294,7.036 93.294,8.585 ; 93.294,7.036 95.25,8.992 ; 93.294,8.585 94.361,8.585 95.25,9.474 ; 95.25,8.992 95.25,9.474 ; 95.25,8.992 98.882,12.624 ; 96.063,31.013 96.063,32.029 ; 96.063,32.029 96.063,34.519 ; 96.063,34.519 96.063,37.516 96.215,37.668 ; 96.215,37.668 99.212,37.668 99.238,37.694 97.777,39.154 ; 98.882,12.624 100.686,14.427 100.686,22.809 98.882,24.613 ; 98.882,12.624 98.882,24.613 ; 200.177,35.179 202.641,37.643 ; 200.177,35.179 200.508,35.179 201.854,35.179 202.641,35.966 202.641,37.313 202.641,37.643 ; 202.184,69.621 202.184,78.003 ; 202.184,69.621 202.184,53.365 202.641,52.908 202.641,37.643 ; 202.184,69.621 203.53,68.275 ; 203.53,55.143 203.53,53.772 204.546,52.756 204.546,39.218 204.546,35.154 ; 203.53,55.143 203.53,68.275 ; 203.53,55.143 205.765,52.908 ; 203.53,68.275 204.8,67.005 ; 204.546,34.036 204.572,34.061 205.765,35.255 ; 204.546,34.036 204.546,34.087 204.546,35.154 ; 204.8,67.005 205.765,66.04 205.765,55.169 ; 204.8,67.005 204.8,56.134 205.765,55.169 ; 205.765,35.255 205.765,52.908 ; 205.765,52.908 205.765,53.106 ; 205.765,53.106 205.765,55.169 ; 218.072,24.092 220.447,26.467 ; 218.643,40.513 218.643,43.104 219.608,44.069 222.199,44.069 ; 218.643,40.513 220.002,41.872 ; 218.643,40.513 218.643,38.481 220.002,37.122 ; 220.002,37.122 220.002,39.332 ; 220.002,37.122 220.447,36.678 220.447,26.467 ; 220.002,39.332 220.002,41.872 ; 220.002,41.872 220.921,42.791 ; 220.921,42.791 222.199,44.069 ; 222.199,44.069 222.656,44.526 ; 222.656,38.964 222.656,44.526 ; 227.076,94.082 227.813,94.818 ; 227.076,94.082 v1(227.813,94.082) 227.813,94.818 ; 227.813,94.818 229.997,97.003 235.052,97.003
  Bottom Layer w2.54: v4(21.031,28.829) 23.139,28.829 26.797,25.171 ; 227.559,5.639 241.097,5.639 246.151,10.693 ; 235.102,24.435 239.065,28.397 ; 237.033,22.936 239.065,24.968 239.065,28.397 ; v2(240.157,18.161) 240.157,26.695 ; 242.57,29.108 240.157,26.695 ; 242.672,32.004 240.157,29.489 ; 243.967,33.884 v2@243.967,34.798 ; 239.065,28.397 240.157,29.489 ; 240.157,26.695 240.157,29.489
  Bottom Layer w3.81: 194.894,24.003 197.51,26.619 197.51,32.182 199.492,34.163 200.508,35.179 201.295,35.966 ; 202.641,35.966 201.295,35.966 ; 204.546,39.802 204.546,39.218 202.641,37.313 201.295,35.966
  Bottom Layer w5.08: 32.436,23.114 32.487,23.114 37.414,28.042 ; 37.77,19.685 37.77,19.736 37.414,20.091 37.414,28.042 ; 41.021,22.174 41.084,22.238 41.084,31.712 ; 45.212,26.01 44.882,26.34 44.882,28.88 ; v4(45.872,33.655) v4(45.872,31.318) 45.872,30.734 48.527,28.08 ; 52.857,22.352 52.857,23.749 48.527,28.08 ; 58.471,23.343 63.424,28.296 63.424,32.728 ; 67,39.085 70.002,42.088 72.136,42.088 ; 70.307,20.498 66.281,24.524 66.281,26.784 ; 71.552,22.962 70.104,22.962 66.281,26.784 ; 73.177,42.088 74.092,42.088 ; C4.2@110.769,77.673 C4.2@112.096,79 ; C4.2@112.5,79 C4.2@112.237,79 ; C4.2@145.5,74 145.5,77.664 143.281,79.883 108.991,79.883 109.874,79 C4.2@112.096,79 ; v2@158.013,37.821 158.013,30.175 163.322,24.867 ; 170.51,28.753 170.548,28.715 176.365,28.715 ; 170.612,34.468 173.634,31.445 ; 172.491,25.806 173.66,26.975 178.105,26.975 ; 180.95,27.788 186.69,22.047 ; 185.242,21.311 184.302,21.311 180.81,24.803 ; 187.681,22.504 187.782,22.504 ; 202.641,35.966 203.759,37.084 ; 204.546,34.087 204.572,34.061 205.765,32.868 ; 205.765,28.524 206.019,28.778 ; 37.414,28.042 41.084,31.712 ; 41.084,31.712 43.866,34.493 44.882,34.493 44.882,28.88 ; 44.882,28.88 45.682,28.08 48.527,28.08 ; 63.424,32.728 64.211,32.728 ; 63.424,32.728 63.424,35.509 64.211,36.297 ; 64.211,28.08 66.281,30.15 ; 64.211,28.08 64.211,32.728 ; 64.211,28.08 64.986,28.08 66.281,26.784 ; 64.211,32.728 66.281,30.658 ; 64.211,32.728 64.211,36.297 ; 64.211,32.728 66.281,34.798 ; 64.211,36.297 66.281,38.367 66.281,34.798 ; 66.281,26.784 66.281,30.15 ; 66.281,30.15 66.281,30.658 ; 66.281,30.658 66.281,34.798 ; 103.403,37.694 99.238,37.694 108.001,46.457 ; 103.403,37.694 106.528,37.694 110.769,41.935 ; 103.403,37.694 108.001,42.291 108.001,44.704 ; 108.001,44.704 108.001,46.457 ; 108.001,44.704 110.769,41.935 ; 108.001,46.457 110.693,49.149 110.769,49.149 110.769,41.935 ; C4.2@112.096,79 C4.2@112.237,79 ; C4.2@112.096,79 112.166,79.07 C4.2@112.237,79 ; 173.634,31.445 181.127,31.445 181.94,30.632 181.94,25.933 180.81,24.803 ; 173.634,31.445 176.365,28.715 ; 176.365,28.715 178.105,26.975 ; 178.105,26.975 178.638,26.975 180.81,24.803
  other v1: 21.438,82.753 63.932,94.132 44.221,94.386 225.069,95.783 6.02,101.752 13.157,105.867
  other v2: 219.888,1.88 212.674,1.905 227.813,1.905 201.676,1.93 209.067,1.93 240.157,1.956 186.792,1.981 205.384,1.981 216.154,1.981 194.335,2.007 223.876,2.007 182.982,2.032 197.917,2.032 190.703,2.057 178.943,2.184 223.774,10.084 190.602,10.135 212.954,10.135 201.803,10.236 194.589,10.262 216.941,10.262 205.791,10.363 258.064,28.397 250.444,28.423 244.018,28.651 243.942,35.738 257.988,35.966 249.784,35.992 166.751,37.44 170.663,37.44 153.797,37.465 158.039,37.465 162.433,37.465 157.861,40.615 162.281,40.615 170.51,40.615 166.624,40.716 153.721,40.843 157.937,43.967 162.357,43.967 170.586,43.967 166.7,44.069 153.797,44.196 140.818,72.365 136.652,72.415 126.365,72.441 131.293,72.466 121.133,72.593 125.73,78.867 120.371,78.918 140.31,78.943 135.026,78.969 129.667,79.019 146.177,79.07 140.259,84.582 134.899,84.684 129.54,84.734 125.247,84.963 119.888,85.014
  other v3: 42.951,49.327 44.399,49.327 243.942,56.21 245.796,56.21 245.796,57.709 243.967,57.734 41.631,60.731 42.901,60.757 44.348,60.757 65.202,60.782 62.662,60.833 63.906,60.884 240.335,115.824 240.36,117.526 6.274,118.008 8.026,118.085 1.346,119.38 13.665,120.802
  other v4: 20.955,5.309 23.368,5.309 21.031,7.747 23.444,7.747 21.082,9.83 23.495,9.83 21.057,11.913 23.47,11.913 21.031,14.199 23.444,14.199 21.031,16.535 23.444,16.535 21.107,18.974 23.52,18.974 21.031,21.133 23.444,21.133 50.648,21.311 43.485,21.336 45.898,21.336 21.057,23.038 23.47,23.038 50.673,23.216 43.51,23.241 45.923,23.241 21.031,24.841 23.444,24.841 50.648,25.019 43.485,25.044 45.898,25.044 21.057,26.746 23.47,26.746 50.673,26.924 43.51,26.949 45.923,26.949 23.444,28.829 49.124,28.931 43.485,29.032 45.898,29.032 43.459,31.318 43.459,33.655 43.536,36.093 45.949,36.093
PT1000_AN1_U1: P1_U1.2 R11_U1.1 | length 4.5
  Top Layer w0.508: R11_U1.1@17.018,55.982 20.93,55.982 21.133,56.185 P1_U1.2@21.438,56.185
PT1000_AN1_U2: P1_U2.2 R11_U2.1 | length 5.3
  Top Layer w0.381: R11_U2.1@138.709,98.044 139.954,96.799 142.926,96.799 P1_U2.2@143.307,97.18
PT1000_AP1_U1: P1_U1.1 R4_U1.2 U1_U1.12 | length 19.9
  Top Layer w0.508: U1_U1.12@4.648,60.731 4.648,61.432 5.446,62.23 10.058,62.23 10.211,62.23 10.668,61.773 16.789,61.773 16.967,61.595 16.967,60.503 R4_U1.2@17.145,60.325 18.745,58.725 P1_U1.1@21.438,58.725
PT1000_AP1_U2: P1_U2.1 R4_U2.2 U1_U2.12 | length 16.8
  Top Layer w0.381: v1(141.745,102.984) 142.786,102.984 R4_U2.2@143.332,102.438 143.332,99.746 P1_U2.1@143.307,99.72 ; v1(144.704,112.243) U1_U2.12@146.431,112.243
  Bottom Layer w0.381: v1(141.745,102.984) 144.094,105.334 144.094,111.633 v1(144.704,112.243)
TEMP_U1: C12_U1.1 P4_U1.29 R5_U1.2 R9_U1.2 | length 124
  Top Layer w0.508: R5_U1.2@3.962,63.5 C12_U1.1@3.962,68.402 ; C12_U1.1@4.089,68.174 4.089,71.374 5.207,72.492 8.001,72.492 v1(9.754,74.244)
  Bottom Layer w0.381: 70.028,117.729 71.107,118.808 71.107,120.764 69.977,121.895 69.977,123.114 71.107,124.244 71.107,126.124 70.092,127.139 P4_U1.29@70.091,129.952
  Bottom Layer w0.508: v1@9.804,74.244 9.804,92.634 ; 10.135,92.964 9.804,92.634 ; 70.028,117.729 69.24,116.942 27.584,116.942 23.317,112.674 23.317,103.378 18.872,98.933 15.951,98.933 9.804,92.786 9.804,92.634
TEMP_U2: C12_U2.1 P4_U2.29 R5_U2.2 R9_U2.2 | length 58.3
  Top Layer w0.381: C12_U2.1@142.596,119.329 142.596,117.17 R9_U2.2@142.646,117.119 R5_U2.2@144.958,117.119 144.958,119.024 v1(144.983,119.05) ; v1(187.376,124.511) 187.401,124.536 189.611,124.536 189.906,124.831 P4_U2.29@189.906,128.047
  Bottom Layer w0.381: v1@145.034,118.999 145.034,120.294 148.92,124.181 183.083,124.181 184.074,125.171 186.715,125.171 v1(187.376,124.511)
U_OUT_U1: C32_U1.2 Q2_U1.3 Q3_U1.2 R30_U1.2 U6_U1.6 U7_U1.1 U7_U1.2 | length 175.4
  Top Layer w0.508: U6_U1.6@33.122,97.942 33.122,95.733 34.112,94.742 34.112,91.669 33.528,91.084 33.528,90.272 33.528,89.281 34.823,87.986 C32_U1.2@35.001,87.986 35.001,87.224 33.757,85.979 33.757,81.915 33.325,81.483 R30_U1.2@33.325,80.67
  Top Layer w0.762: R30_U1.2@33.325,80.67 33.325,77.749 36,75.074 Q2_U1.3@36,74
  Top Layer w2.032: 28.245,46.025 Q3_U1.2@30.44,48.22 ; Q3_U1.2@30.44,50 Q3_U1.2@30.44,48.529 ; 30.582,44.958 30.44,45.1 Q3_U1.2@30.44,48.22 ; 33.02,45.949 Q3_U1.2@30.44,48.529 ; Q3_U1.2@30.44,48.22 Q3_U1.2@30.44,48.529
  Bottom Layer w2.032: Q2_U1.3@36,74 Q2_U1.3@36,73.389 ; 29.21,52.857 Q3_U1.2@30.44,51.627 ; 29.21,52.857 27.737,54.331 27.737,67.589 29.705,69.558 32.169,69.558 ; 29.21,52.857 29.21,62.586 ; 29.21,52.857 29.21,51.23 Q3_U1.2@30.44,50 ; 29.21,62.586 29.21,64.948 ; 29.21,62.586 33.122,66.497 33.122,68.859 ; 29.21,64.948 29.21,66.599 32.169,69.558 ; 29.21,64.948 33.122,68.859 ; Q3_U1.2@30.44,50 Q3_U1.2@30.44,51.627 ; Q3_U1.2@30.44,50 32.334,51.894 32.334,53.416 ; Q3_U1.2@30.44,51.627 30.44,61.022 34.519,65.1 34.519,69.774 36,71.255 ; 32.169,69.558 33.122,70.51 ; 32.334,53.416 32.334,55.143 ; 32.334,53.416 36,57.082 36,58.809 ; 32.334,55.143 32.334,57.658 ; 32.334,55.143 36,58.809 ; 32.334,57.658 32.334,60.325 36,63.991 ; 32.334,57.658 36,61.324 ; 33.122,68.859 33.122,70.51 ; 33.122,70.51 Q2_U1.3@36,73.389 ; 36,58.809 36,61.324 ; 36,61.324 36,63.991 ; 36,63.991 36,71.255 ; 36,71.255 Q2_U1.3@36,73.389
U_OUT_U2: C32_U2.2 Q2_U2.3 Q3_U2.2 R30_U2.2 U6_U2.6 U7_U2.1 U7_U2.2 | length 173.3
  Top Layer w0.508: R30_U2.2@193.218,77.927 193.218,83.083 194.843,84.709 C32_U2.2@194.843,85.344 ; U6_U2.6@194.005,96.52 194.005,93.853 194.005,89.51 193.7,89.205 193.7,86.995 C32_U2.2@194.97,85.725
  Top Layer w0.762: R30_U2.2@193.218,77.927 193.218,76.479 196.021,73.677 Q2_U2.3@196.021,72.898
  Top Layer w2.032: 187.884,45.085 Q3_U2.2@190.539,47.74 ; Q3_U2.2@190.539,48.931 Q3_U2.2@190.539,47.74 ; 190.551,44.526 190.539,44.538 Q3_U2.2@190.539,47.536 ; 191.795,43.51 191.999,43.713 191.999,46.076 Q3_U2.2@190.539,47.536 ; Q3_U2.2@190.539,47.536 Q3_U2.2@190.539,47.74
  Bottom Layer w2.032: 188.951,59.487 188.951,50.361 Q3_U2.2@190.481,48.83 ; 188.951,59.487 188.951,64.211 190.678,65.938 ; 188.951,59.487 190.678,61.214 190.678,65.938 ; Q3_U2.2@190.481,48.83 190.481,53.613 ; Q3_U2.2@190.481,48.83 190.714,48.83 191.618,49.733 191.618,53.035 ; 190.481,53.613 190.481,54.007 ; 190.481,53.613 191.555,54.686 191.618,54.686 ; 190.481,54.007 191.389,54.915 ; 190.481,54.007 190.481,55.822 ; 190.481,55.822 190.481,58.185 ; 190.481,55.822 191.389,54.915 ; 190.481,58.185 191.618,57.048 ; 190.481,58.185 190.481,58.351 191.973,59.842 ; 190.678,65.938 192.329,67.589 ; 191.389,54.915 191.618,55.143 ; 191.389,54.915 191.618,54.686 ; 191.618,53.035 191.618,54.686 ; 191.618,53.035 192.443,53.861 ; 191.618,54.686 191.618,55.143 ; 191.618,54.686 192.443,53.861 ; 191.618,55.143 191.618,57.048 ; 191.618,55.143 196.021,59.546 196.021,61.629 ; 191.618,57.048 191.973,57.404 191.973,57.582 ; 191.618,57.048 191.618,57.226 191.973,57.582 ; 191.973,57.582 196.021,61.629 ; 191.973,57.582 191.973,59.842 ; 191.973,59.842 192.329,60.198 ; 192.329,60.198 194.183,62.052 194.183,69.181 ; 192.329,60.198 192.329,67.589 ; 192.329,67.589 194.183,69.444 ; 192.443,53.861 196.901,58.318 196.901,72.018 Q2_U2.3@196.021,72.898 ; 194.183,69.181 194.183,69.444 ; 194.183,69.181 196.021,71.018 ; 194.183,69.444 194.183,71.06 Q2_U2.3@196.021,72.898 ; 196.021,61.629 196.021,71.018 ; 196.021,71.018 Q2_U2.3@196.021,72.898
UU_OUT1: U7_U1.3 U7_U1.4 U15.1 | length 452.1
  Top Layer w2.032: 31.42,41.173 31.801,41.173 33.376,39.599 ; 31.521,24.257 35.001,27.737 ; U7_U1.4@32.817,41.377 33.782,41.377 ; 33.376,40.361 33.376,39.599 ; 35.001,28.55 35.001,27.737 ; 35.001,33.706 35.001,30.861 ; 35.471,39.688 35.23,39.929 ; 39.802,14.783 39.751,14.783 ; 87.554,4.216 88.443,4.216 95.682,11.455 ; 89.103,7.468 93.091,11.455 ; U15.1@133.741,4.663 U15.1@133.741,5.248 ; 33.376,39.599 35.001,37.973 35.001,30.861 ; 33.782,41.377 35.23,39.929 ; 33.782,41.377 34.493,42.088 35.23,42.088 35.23,39.929 ; 35.001,27.737 35.001,15.443 38.989,11.455 93.091,11.455 ; 35.001,27.737 35.001,30.861 ; 35.23,39.929 36.754,38.405 ; 36.754,38.405 38.278,36.881 38.278,16.256 39.751,14.783 ; 36.754,38.405 36.754,16.053 40.869,11.938 93.574,11.938 ; 39.751,14.783 41.072,13.462 102.921,13.462 ; 93.091,11.455 95.682,11.455 ; 93.091,11.455 93.574,11.938 ; 93.574,11.938 96.164,11.938 ; 95.682,11.455 103.226,11.455 105.41,9.271 ; 95.682,11.455 96.164,11.938 ; 96.164,11.938 104.445,11.938 ; 102.921,13.462 104.318,13.462 ; 102.921,13.462 104.445,11.938 ; 104.318,13.462 129.184,13.462 133.741,8.905 133.741,7.051 ; 104.318,13.462 106.172,11.608 ; 104.445,11.938 105.918,10.465 106.604,10.465 ; 105.41,9.271 129.718,9.271 ; 105.41,9.271 106.604,10.465 ; 106.172,11.608 107.315,10.465 ; 106.172,11.608 129.184,11.608 130.327,10.465 ; 106.604,10.465 107.315,10.465 ; 107.315,10.465 128.524,10.465 ; 128.524,10.465 129.718,9.271 ; 128.524,10.465 130.327,10.465 ; 129.718,9.271 U15.1@133.741,5.248 ; 129.718,9.271 131.521,9.271 ; 130.327,10.465 131.521,9.271 ; 131.521,9.271 133.741,7.051 ; U15.1@133.741,5.248 133.741,7.051
UU_OUT2: U7_U2.3 U7_U2.4 U15.4 | length 201.7
  Top Layer w2.032: U15.4@149.341,4.663 U15.4@149.341,5.349 ; 187.198,40.945 184.582,40.945 183.007,39.37 183.007,36.373 179.375,32.741 153.086,32.741 148.209,27.864 148.209,6.782 U15.4@149.341,5.65 ; U15.4@149.341,5.349 U15.4@149.341,5.65 ; U15.4@149.341,5.349 150.52,6.528 150.52,26.06 154.711,30.251 181.356,30.251 185.471,34.366 185.471,37.262 187.655,39.446 185.598,39.446 184.328,38.176 184.328,35.763 179.959,31.394 153.67,31.394 149.341,27.066 U15.4@149.341,5.65
V_OUT_U1: C47_U1.1 Q4_U1.3 Q5_U1.2 R47_U1.1 U9_U1.6 U10_U1.1 U10_U1.2 | length 161
  Top Layer w0.762: U9_U1.6@54.127,97.942 54.102,97.917 54.102,96.241 54.686,95.656 54.686,89.687 56.032,88.341 C47_U1.1@56.032,88.214 56.032,81.763 55.677,81.407 R47_U1.1@55.677,80.797 55.677,76.937 57,75.613 Q4_U1.3@57,74
  Top Layer w2.032: 53.188,45.974 Q5_U1.2@55.44,48.226 ; 55.423,45.72 55.44,45.737 55.44,48.141 ; Q5_U1.2@55.44,50 Q5_U1.2@55.44,48.226 ; 57.582,45.999 55.44,48.141 ; 55.44,48.141 Q5_U1.2@55.44,48.226
  Bottom Layer w2.032: 53.162,69.088 56.769,72.695 Q4_U1.3@56.769,73.558 ; 55.44,57.209 Q5_U1.2@55.44,51.265 ; 51.74,54.966 50.368,56.337 50.368,67.335 52.121,69.088 53.772,69.088 ; 51.74,54.966 54.026,52.68 ; 51.74,54.966 51.74,67.056 53.772,69.088 ; 53.772,69.088 54.026,69.342 ; 53.772,69.088 54.026,69.088 ; 54.026,52.68 54.026,69.088 ; 54.026,52.68 54.026,50.19 55.25,50.19 Q5_U1.2@55.44,50 ; 54.026,52.68 Q5_U1.2@55.44,51.265 ; 54.026,69.088 54.026,69.342 ; 54.026,69.088 55.27,69.088 ; 54.026,69.342 55.27,70.587 ; 55.27,69.088 55.27,70.587 ; 55.27,69.088 55.27,59.233 56.769,57.734 ; 55.27,70.587 56.769,72.085 ; Q5_U1.2@55.44,50 Q5_U1.2@55.44,51.265 ; Q5_U1.2@55.44,50 56.477,50 56.769,50.292 56.769,57.734 ; 56.769,57.734 56.769,65.253 ; 56.769,65.253 56.769,72.085 ; 56.769,65.253 57,65.484 Q4_U1.3@57,72.316 ; 56.769,72.085 Q4_U1.3@56.769,73.558 ; 56.769,72.085 Q4_U1.3@57,72.316 ; Q4_U1.3@56.769,73.558 56.769,73.769 57,74 Q4_U1.3@57,73.789 ; Q4_U1.3@56.769,73.558 Q4_U1.3@57,73.789 ; Q4_U1.3@57,72.316 Q4_U1.3@57,73.789
V_OUT_U2: C47_U2.1 Q4_U2.3 Q5_U2.2 R47_U2.1 U9_U2.6 U10_U2.1 U10_U2.2 | length 157.8
  Top Layer w0.508: U9_U2.6@213.589,96.52 213.589,95.174 214.808,93.955 214.808,90.119 214.427,89.738 ; R47_U2.1@213.665,77.521 213.665,82.474 215.824,84.633 C47_U2.1@215.824,85.852 214.427,87.249 214.427,89.738 ; 214.427,89.764 214.427,89.738
  Top Layer w0.762: R47_U2.1@213.665,77.521 213.665,76.556 217.026,73.194 Q4_U2.3@217.026,72.822
  Top Layer w2.032: 212.827,44.983 Q5_U2.2@215.481,47.638 ; Q5_U2.2@215.481,48.83 Q5_U2.2@215.481,47.638 ; 215.494,44.425 215.481,44.437 Q5_U2.2@215.481,47.434 ; 216.738,43.409 216.941,43.612 216.941,45.974 Q5_U2.2@215.481,47.434 ; Q5_U2.2@215.481,47.434 Q5_U2.2@215.481,47.638
  Bottom Layer w2.032: 212.471,53.81 213.328,52.953 ; 212.471,53.81 211.48,54.8 211.48,65.608 213.328,67.456 ; 212.471,53.81 213.328,53.81 ; 213.328,52.953 214.579,51.702 214.579,49.047 214.797,48.83 Q5_U2.2@215.481,48.83 ; 213.328,52.953 213.328,53.81 ; 213.328,53.81 213.728,53.81 215.214,52.324 ; 213.328,53.81 213.328,67.456 ; 213.328,67.456 215.214,69.342 ; 215.214,52.324 215.214,69.342 ; 215.214,52.324 215.481,52.057 Q5_U2.2@215.481,48.83 ; 215.214,69.342 215.214,71.01 Q4_U2.3@217.026,72.822 ; Q5_U2.2@215.481,48.83 216.753,48.83 216.865,48.717 216.865,52.121 ; 216.865,52.121 216.865,53.492 ; 216.865,52.121 217.856,53.111 217.856,55.55 ; 216.865,53.492 215.278,55.08 217.026,56.829 Q4_U2.3@217.026,72.822 ; 216.865,53.492 216.865,54.559 217.856,55.55 ; Q4_U2.3@217.026,72.822 217.856,71.992 217.856,55.55
VAL_CTRL_U1: P4_U1.7
VAL_CTRL_U2: P4_U2.7
VDC1_U1: P4_U1.14 R83_U1.2 U13_U1.7 | length 44.1
  Top Layer w0.508: P4_U1.14@69.139,128.047 69.139,124.13 69.545,123.723 80.035,123.723 80.315,123.444 v1(80.315,122.022) 80.62,122.022 82.309,120.332 82.309,118.402 82.931,117.78 95.326,117.78 95.783,117.323 95.783,114.605 95.174,113.995 U13_U1.7@93.904,113.995 ; R83_U1.2@78.791,119.507 v1(80.239,119.507)
  Bottom Layer w0.508: v1@80.315,119.507 v1@80.315,121.971
VDC1_U2: P4_U2.14 R83_U2.2 U13_U2.7 | length 83.5
  Top Layer w0.381: P4_U2.14@190.858,129.952 190.858,126.286 194.462,122.682 v1(194.589,122.682) ; v1(253.035,100.609) 253.06,100.609 255.295,98.374 U13_U2.7@255.295,97.815
  Top Layer w0.762: U13_U2.7@255.295,97.815 255.295,96.19 256.235,95.25 R83_U2.2@256.235,94.92
  Bottom Layer w0.381: v1(194.589,122.682) 202.565,122.682 204.851,120.396 223.926,120.396 237.084,107.239 243.408,107.239 250.038,100.609 v1(253.035,100.609)
VREF_2V5_U1: C2_U1.1 C3_U1.1 R3_U1.1 R4_U1.1 U2_U1.2 | length 27.9
  Top Layer w1.016: U2_U1.2@8.89,49.276 8.89,47.574 9.728,46.736 v1(9.728,46.787) 10.109,46.406 C3_U1.1@16.104,46.406 ; v1(10.998,60.452) R3_U1.1@12.573,60.452
  Top Layer w1.27: R3_U1.1@12.7,60.325 R4_U1.1@14.757,60.325
  Bottom Layer w1.016: v1(9.728,46.787) 9.728,48.819 10.77,49.86 ; 10.795,49.86 11.684,50.749 11.684,52.014 11.697,52.026 11.697,55.131 10.998,55.829 v1(10.998,60.452)
VREF_2V5_U2: C2_U2.1 C3_U2.1 R3_U2.1 R4_U2.1 U2_U2.2 | length 31.6
  Top Layer w0.762: v1(131.953,99.72) 131.953,101.422 C3_U2.1@132.004,101.473 ; R4_U2.1@145.72,102.438 v1(146.939,102.438) 147.726,103.226 R3_U2.1@147.726,104.8
  Top Layer w1.27: C3_U2.1@132.004,101.473 131.623,101.854 131.623,108.153 132.309,108.839 U2_U2.2@134.264,108.839
  Bottom Layer w0.762: v1(131.953,99.72) 136.55,99.72 138.659,101.829 142.291,101.829 142.9,102.438 v1(146.939,102.438)
VV_OUT1: U10_U1.3 U10_U1.4 U15.2 | length 359.8
  Top Layer w2.032: 57.556,41.758 57.836,41.758 ; 58.115,40.005 59.766,38.354 59.766,23.216 65.1,17.882 131.267,17.882 132.207,16.942 ; 73.711,23.749 77.597,19.863 ; 81.636,19.863 77.597,19.863 ; 127.584,18.923 127.127,18.466 66.37,18.466 61.214,23.622 61.214,33.63 61.214,38.379 ; 135.179,16.586 138.941,12.824 ; 57.836,41.758 60.122,39.472 ; 57.836,41.758 59.893,41.758 60.122,41.529 60.122,39.472 ; 60.122,39.472 61.214,38.379 ; 61.214,38.379 62.586,37.008 62.586,32.258 62.586,24.562 64.732,22.415 67.285,19.863 77.597,19.863 ; 77.597,19.863 131.877,19.863 138.941,12.798 138.941,11.503 ; 132.207,16.942 137.986,11.163 ; 132.207,16.942 133.502,16.942 138.941,11.503 ; 137.986,11.163 138.941,10.208 ; 137.986,11.163 137.986,5.619 138.941,4.663 138.941,10.208 ; 138.941,10.208 138.941,11.503
  Top Layer w2.54: 61.214,34.925 61.214,33.63 62.586,32.258 64.732,30.112 ; 64.732,22.415 64.732,30.112 ; 67.107,22.504 66.37,23.241 66.37,28.423 ; 71.831,22.962 66.37,28.423 ; 64.732,30.112 66.37,28.473 66.37,28.423
VV_OUT2: U10_U2.3 U10_U2.4 U15.5 | length 318.1
  Top Layer w2.032: 211.557,39.268 207.696,39.268 205.207,36.779 205.207,30.175 199.974,24.943 199.492,24.943 ; 212.192,40.869 206.807,40.869 203.454,37.516 ; 213.157,39.141 211.988,37.973 ; 154.541,10.422 155.207,11.087 ; 154.541,10.422 154.541,4.663 155.207,5.328 155.207,11.087 ; 154.541,10.422 154.541,12.631 161.569,19.66 ; 155.207,11.087 166.116,21.996 ; 161.569,19.66 164.922,23.012 167.132,23.012 ; 161.569,19.66 161.569,22.2 164.313,24.943 184.887,24.943 186.334,23.495 ; 166.116,21.996 168.148,21.996 ; 166.116,21.996 167.132,23.012 ; 167.132,23.012 168.148,21.996 ; 167.132,23.012 167.615,23.495 186.334,23.495 ; 168.148,21.996 196.545,21.996 ; 186.334,23.495 194.361,23.495 ; 194.361,23.495 196.063,23.495 197.51,24.943 ; 194.361,23.495 197.091,26.226 ; 196.545,21.996 199.492,24.943 ; 196.545,21.996 198.628,21.996 ; 197.091,26.226 197.091,31.153 198.285,32.347 ; 197.091,26.226 198.285,27.419 ; 197.51,24.943 203.454,30.886 203.454,37.516 ; 197.51,24.943 199.492,24.943 ; 198.285,27.419 198.285,32.347 ; 198.285,27.419 199.936,29.07 ; 198.285,32.347 199.936,33.998 ; 198.628,21.996 207.01,30.378 ; 198.628,21.996 201.371,21.996 ; 199.936,29.07 199.936,33.998 ; 199.936,29.07 201.778,30.912 201.778,35.839 ; 199.936,33.998 201.778,35.839 ; 201.371,21.996 207.01,27.635 ; 201.371,21.996 203.479,21.996 ; 201.778,35.839 203.454,37.516 ; 203.479,21.996 205.969,21.996 209.499,25.527 209.499,28.016 ; 203.479,21.996 207.01,25.527 ; 207.01,25.527 207.01,27.635 ; 207.01,25.527 207.835,26.352 ; 207.01,27.635 207.01,30.378 ; 207.01,30.378 207.01,35.789 207.835,36.614 ; 207.835,26.352 207.835,36.614 ; 207.835,26.352 209.499,28.016 ; 207.835,36.614 209.194,37.973 211.988,37.973 ; 209.499,28.016 209.499,35.484 211.988,37.973
W_OUT_U1: C54_U1.1 Q7_U1.3 Q8_U1.2 R62_U1.1 U11_U1.6 U12_U1.1 U12_U1.2 | length 160.3
  Top Layer w0.508: U11_U1.6@73.838,97.968 73.838,97.104 75.59,95.352 75.59,88.951 76.505,88.036 76.606,88.036 C54_U1.1@76.937,88.036
  Top Layer w0.762: C54_U1.1@76.606,88.036 76.606,86.131 76.073,85.598 R62_U1.1@76.073,80.035 76.073,78.384 78,76.457 Q7_U1.3@78,74
  Top Layer w2.032: 70.46,46.482 Q8_U1.2@72.44,48.462 ; 72.263,45.009 72.44,45.186 Q8_U1.2@72.44,48.462 ; Q8_U1.2@72.44,50 Q8_U1.2@72.44,48.464 ; 74.968,45.936 Q8_U1.2@72.44,48.464 ; Q8_U1.2@72.44,48.462 Q8_U1.2@72.44,48.464
  Bottom Layer w2.032: 72.44,56.287 72.44,63.169 ; 69.393,54.407 68.097,55.702 68.097,58.242 69.393,59.538 ; 69.393,54.407 70.65,53.149 ; 69.393,54.407 69.393,57.201 ; 69.393,57.201 69.393,59.538 ; 69.393,57.201 70.65,55.944 ; 69.393,59.538 69.393,64.846 ; 69.393,64.846 69.393,67.234 70.891,68.732 73.279,68.732 ; 69.393,64.846 70.79,66.243 ; 70.65,53.149 71.044,52.756 71.044,51.396 72.44,50 Q8_U1.2@72.44,50.342 ; 70.65,53.149 70.65,55.639 ; 70.65,55.639 70.65,55.944 ; 70.65,55.639 72.44,53.849 ; 70.65,55.944 70.79,56.083 70.79,66.243 ; 70.79,66.243 73.279,68.732 ; Q8_U1.2@72.44,50.342 72.44,53.849 ; Q8_U1.2@72.44,50.342 74.041,51.943 74.041,54.331 72.44,55.932 72.44,53.849 ; 72.44,63.169 75.908,66.637 ; 72.44,63.169 72.44,65.938 75.032,68.529 ; 73.279,68.732 76.454,71.907 ; 73.279,68.732 74.828,68.732 75.032,68.529 ; 75.032,68.529 76.454,69.952 76.454,71.907 ; 75.908,66.637 78,68.729 Q7_U1.3@78,73.965 ; 75.908,66.637 77.203,66.637 79.959,69.393 79.959,72.041 ; 76.454,71.907 76.454,72.454 ; 76.454,72.454 Q7_U1.3@77.965,73.965 ; 76.454,72.454 76.454,73.939 76.733,74.219 76.987,73.965 Q7_U1.3@77.965,73.965 ; Q7_U1.3@77.965,73.965 Q7_U1.3@78,73.965 ; Q7_U1.3@77.965,73.965 Q7_U1.3@78,74 ; Q7_U1.3@78,73.965 Q7_U1.3@78,74 ; Q7_U1.3@78,73.965 Q7_U1.3@78.038,73.965 ; Q7_U1.3@78,74 Q7_U1.3@78.038,73.965 ; Q7_U1.3@78.038,73.965 Q7_U1.3@78.038,73.965 79.451,73.965 79.629,74.143 79.959,73.812 79.959,72.041 ; Q7_U1.3@78.038,73.965 79.959,72.041
W_OUT_U2: C54_U2.1 Q7_U2.3 Q8_U2.2 R62_U2.1 U11_U2.6 U12_U2.1 U12_U2.2 | length 152.4
  Top Layer w0.508: U11_U2.6@233.858,96.495 233.858,95.631 235.585,93.904 235.585,88.697 235.585,86.309 236.068,85.827 C54_U2.1@237.134,85.827 237.134,79.045 R62_U2.1@236.779,78.689
  Top Layer w0.762: R62_U2.1@236.779,78.689 236.779,75.59 238.032,74.337 Q7_U2.3@238.032,72.771
  Top Layer w2.032: 229.489,43.409 229.464,43.434 229.464,44.475 229.997,44.475 232.481,46.96 ; 232.481,43.663 232.481,46.919 ; Q8_U2.2@232.481,48.83 232.481,46.96 ; 234.061,43.536 234.061,45.339 232.481,46.919 ; 232.481,46.919 232.481,46.96
  Bottom Layer w2.032: 234.315,56.896 234.315,55.499 ; 231.115,57.404 231.115,59.639 ; 231.115,57.404 231.115,48.895 231.18,48.83 Q8_U2.2@232.481,48.83 ; 231.115,57.404 233.223,59.512 233.223,66.599 ; 231.115,59.639 231.115,64.491 231.851,65.227 ; 231.115,59.639 231.851,60.376 231.851,65.227 ; 231.851,65.227 233.223,66.599 ; Q8_U2.2@232.481,48.83 232.481,56.332 235.052,58.903 235.052,68.428 ; Q8_U2.2@232.481,48.83 232.492,48.819 233.832,48.819 234.315,49.301 234.315,52.883 ; 233.223,66.599 235.052,68.428 ; 234.315,52.883 234.315,55.499 ; 234.315,52.883 238.506,57.074 238.506,72.297 Q7_U2.3@238.032,72.771 236.652,71.391 236.652,70.028 ; 234.315,55.499 236.652,57.836 236.652,70.028 ; 235.052,68.428 236.652,70.028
